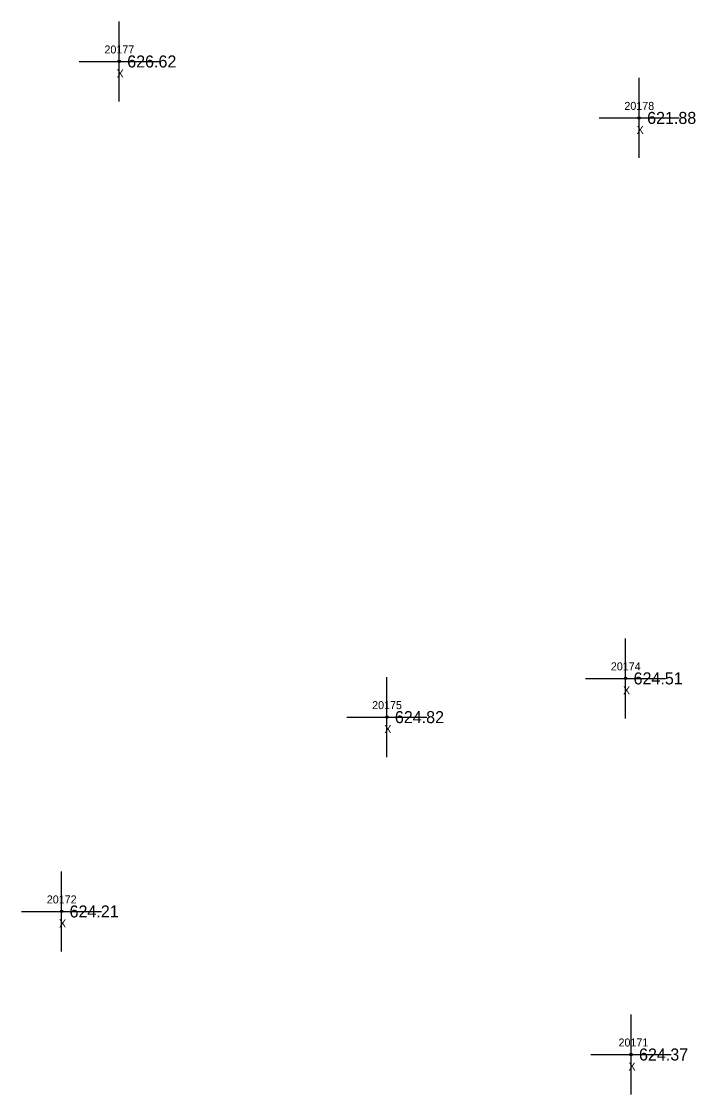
# Model space of a CAD drawing. Extents: x 1695443 to 1696344, y 1087542 to 1090645.
# Drawn here: x 1695797.9 to 1695882.1, y 1088185.6 to 1088319.6 of the extents above; entities that cross this region are included whole.
import ezdxf

# ---------------------------------------------------------------- set-up
doc = ezdxf.new("R2010")
doc.units = 0
for name, color, linetype in [('RD_EX_Misc', 7, 'Continuous'), ('RD_EX_Misc_txCode', 7, 'Continuous'), ('RD_EX_TX_Misc_ELEV', 7, 'Continuous'), ('RD_SMD_Locator', 7, 'Continuous')]:
    doc.layers.add(name, color=color, linetype=linetype)

msp = doc.modelspace()

# ---------------------------------------------------------------- linework, layer by layer
at = {"layer": 'RD_EX_Misc'}
for p, q in [((1695810.08, 1088309.65), (1695810.08, 1088319.65)), ((1695805.08, 1088314.65), (1695815.08, 1088314.65)), ((1695875.01, 1088302.6), (1695875.01, 1088312.6)), ((1695870.01, 1088307.6), (1695880.01, 1088307.6)), ((1695873.32, 1088232.59), (1695873.32, 1088242.59)), ((1695843.51, 1088227.75), (1695843.51, 1088237.75)), ((1695868.32, 1088237.59), (1695878.32, 1088237.59)), ((1695838.51, 1088232.75), (1695848.51, 1088232.75)), ((1695802.88, 1088203.48), (1695802.88, 1088213.48)), ((1695797.88, 1088208.48), (1695807.88, 1088208.48)), ((1695874, 1088185.61), (1695874, 1088195.61)), ((1695869, 1088190.61), (1695879, 1088190.61))]:
    msp.add_line(p, q, dxfattribs=at)
at = {"layer": 'RD_SMD_Locator'}
for centre in [(1695810.08, 1088314.65), (1695875.01, 1088307.6), (1695873.32, 1088237.59), (1695843.51, 1088232.75), (1695802.88, 1088208.48), (1695874, 1088190.61)]:
    msp.add_circle(centre, 0.15, dxfattribs=at)

# ---------------------------------------------------------------- texts
at = {"layer": 'RD_EX_Misc_txCode'}
for s, p in [('20177', (1695808.24, 1088315.65)), ('X', (1695809.76, 1088312.65)), ('20178', (1695873.17, 1088308.6)), ('X', (1695874.69, 1088305.6)), ('20174', (1695871.48, 1088238.59)), ('X', (1695873, 1088235.59)), ('20175', (1695841.67, 1088233.75)), ('X', (1695843.19, 1088230.75)), ('20172', (1695801.04, 1088209.48)), ('X', (1695802.56, 1088206.48)), ('20171', (1695872.44, 1088191.61)), ('X', (1695873.68, 1088188.61))]:
    msp.add_text(s, height=1, dxfattribs=at).set_placement(p)
at = {"layer": 'RD_EX_TX_Misc_ELEV'}
for s, p in [('626.62', (1695811.08, 1088313.9)), ('621.88', (1695876.01, 1088306.85)), ('624.51', (1695874.32, 1088236.84)), ('624.82', (1695844.51, 1088232)), ('624.21', (1695803.88, 1088207.73)), ('624.37', (1695875, 1088189.86))]:
    msp.add_text(s, height=1.5, dxfattribs=at).set_placement(p)

doc.saveas('drawing.dxf')
